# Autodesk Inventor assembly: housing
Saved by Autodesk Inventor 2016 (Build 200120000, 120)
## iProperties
Created: 2018-05
Part Number: housing
Document SubType Name: Assembly
Designer: Administrator
Title: housing
Author: Administrator
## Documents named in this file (2)
- c:\worker\convert-fusion-mar-2018\tmp\job-1\16\output\files\8c58ff39-88bb-4352-afd9-60265520bae5\housing.iam
- c:\worker\convert-fusion-mar-2018\tmp\job-1\16\output\files\8c58ff39-88bb-4352-afd9-60265520bae5\shell.ipt
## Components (1 placed, 1 different names)
1. shell:1
